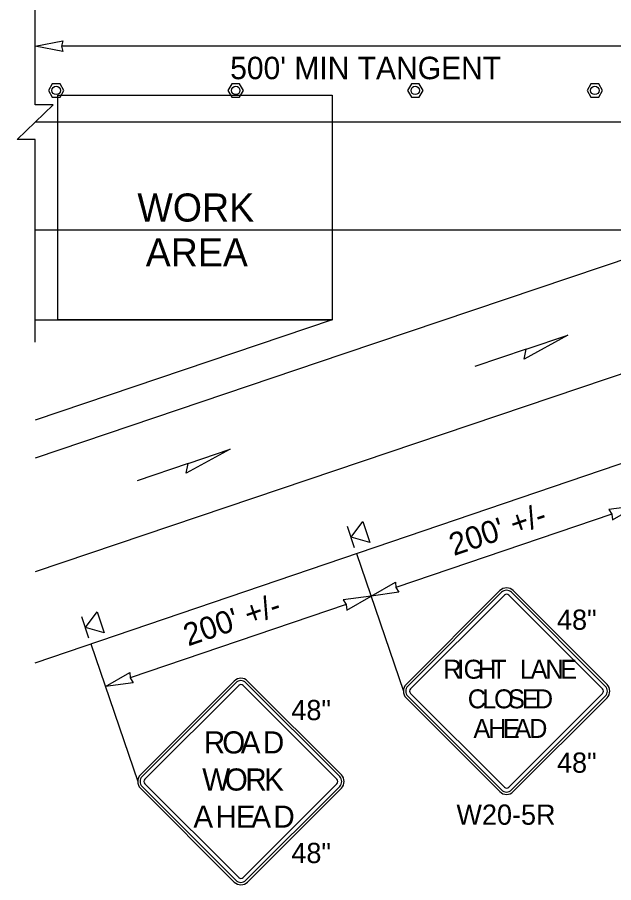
# Model space of a CAD drawing. Extents: x 99999 to 100116, y 99995 to 100013.
# Drawn here: x 100068.131 to 100070.257, y 100004.786 to 100007.868 of the extents above; entities that cross this region are included whole.
import ezdxf

# ---------------------------------------------------------------- set-up
doc = ezdxf.new("R2010")
doc.units = 0
for name, color, linetype in [('RD_MK_LineEdgeYellow', 7, 'Continuous'), ('RD_MK_LineLane', 7, 'Continuous'), ('TR_SN_ConstructionSigns', 7, 'Continuous'), ('TR_WZ_PortableSignMountBlk-Org', 7, 'Continuous'), ('TR_WZ_TallChanDevice', 7, 'Continuous'), ('TR_WZ_WorkAreaLabel', 7, 'Continuous'), ('TR_WZ_WorkZoneDetails', 7, 'Continuous'), ('TR_WZ_WorkZoneTextCurrent', 7, 'Continuous')]:
    doc.layers.add(name, color=color, linetype=linetype)

msp = doc.modelspace()

# ---------------------------------------------------------------- linework, layer by layer
at = {"layer": 'RD_MK_LineEdgeYellow'}
for p, q in [((100068.195, 100007.1109), (100069.2533, 100007.1109)), ((100070.6655, 100006.7269), (100068.195, 100005.8927)), ((100069.2943, 100006.6692), (100068.195, 100006.298))]:
    msp.add_line(p, q, dxfattribs=at)
at = {"layer": 'RD_MK_LineLane'}
msp.add_lwpolyline([(100075.43, 100007.4949), (100068.195, 100007.4949)], dxfattribs=at)
at = {"layer": 'TR_SN_ConstructionSigns'}
for p, q in [((100069.8509, 100005.8261), (100069.5168, 100005.492)), ((100069.8568, 100005.8202), (100069.5227, 100005.4861)), ((100070.2267, 100005.4861), (100069.8926, 100005.8202)), ((100070.2327, 100005.492), (100069.8986, 100005.8261)), ((100069.5327, 100005.4761), (100069.8668, 100005.8102)), ((100069.8827, 100005.8102), (100070.2168, 100005.4761)), ((100068.9041, 100005.5043), (100068.57, 100005.1702)), ((100068.91, 100005.4983), (100068.5759, 100005.1642)), ((100068.5859, 100005.1543), (100068.92, 100005.4884)), ((100068.9359, 100005.4884), (100069.27, 100005.1543)), ((100069.28, 100005.1642), (100068.9458, 100005.4983)), ((100069.2859, 100005.1702), (100068.9518, 100005.5043)), ((100069.5227, 100005.4503), (100069.8568, 100005.1162)), ((100069.8668, 100005.1261), (100069.5327, 100005.4602)), ((100070.2168, 100005.4602), (100069.8827, 100005.1261)), ((100069.8926, 100005.1162), (100070.2267, 100005.4503)), ((100069.5168, 100005.4443), (100069.8509, 100005.1102)), ((100069.8986, 100005.1102), (100070.2327, 100005.4443)), ((100068.57, 100005.1224), (100068.9041, 100004.7883)), ((100068.5759, 100005.1284), (100068.91, 100004.7943)), ((100068.92, 100004.8043), (100068.5859, 100005.1384)), ((100069.27, 100005.1384), (100068.9359, 100004.8043)), ((100068.9458, 100004.7943), (100069.28, 100005.1284)), ((100068.9518, 100004.7883), (100069.2859, 100005.1224))]:
    msp.add_line(p, q, dxfattribs=at)
for centre, radius, start, end in [((100069.8747, 100005.8023), 0.0338, 45, 135), ((100069.8747, 100005.8023), 0.0253, 45, 135), ((100069.8747, 100005.8023), 0.0113, 45, 135), ((100068.9279, 100005.4804), 0.0338, 45, 135), ((100068.9279, 100005.4804), 0.0253, 45, 135), ((100068.9279, 100005.4804), 0.0113, 45, 135), ((100069.5406, 100005.4682), 0.0338, 135, 225), ((100069.5406, 100005.4682), 0.0253, 135, 225), ((100070.2088, 100005.4682), 0.0253, 315, 45), ((100070.2088, 100005.4682), 0.0338, 315, 45), ((100069.5406, 100005.4682), 0.0113, 135, 225), ((100070.2088, 100005.4682), 0.0113, 315, 45), ((100068.5938, 100005.1463), 0.0338, 135, 225), ((100068.5938, 100005.1463), 0.0253, 135, 225), ((100068.5938, 100005.1463), 0.0113, 135, 225), ((100069.2621, 100005.1463), 0.0113, 315, 45), ((100069.2621, 100005.1463), 0.0253, 315, 45), ((100069.2621, 100005.1463), 0.0338, 315, 45), ((100069.8747, 100005.1341), 0.0338, 225, 315), ((100069.8747, 100005.1341), 0.0253, 225, 315), ((100069.8747, 100005.1341), 0.0113, 225, 315), ((100068.9279, 100004.8122), 0.0113, 225, 315), ((100068.9279, 100004.8122), 0.0338, 225, 315), ((100068.9279, 100004.8122), 0.0253, 225, 315)]:
    msp.add_arc(centre, radius, start, end, dxfattribs=at)
at = {"layer": 'TR_WZ_PortableSignMountBlk-Org'}
for p, q in [((100069.3333, 100005.9787), (100069.3076, 100006.0545)), ((100068.3865, 100005.6569), (100068.3608, 100005.7326))]:
    msp.add_line(p, q, dxfattribs=at)
for points in [[(100069.3205, 100006.0165), (100069.362, 100006.0729), (100069.3877, 100005.9972)], [(100068.3737, 100005.6947), (100068.4152, 100005.7511), (100068.4409, 100005.6753)]]:
    msp.add_lwpolyline(points, close=True, dxfattribs=at)
at = {"layer": 'TR_WZ_TallChanDevice'}
for points in [[(100068.2833, 100007.6319), (100068.2555, 100007.6319), (100068.2417, 100007.6079), (100068.2555, 100007.5839), (100068.2833, 100007.5839), (100068.2971, 100007.6079)], [(100068.9233, 100007.6319), (100068.8955, 100007.6319), (100068.8817, 100007.6079), (100068.8955, 100007.5839), (100068.9233, 100007.5839), (100068.9371, 100007.6079)], [(100069.5633, 100007.6319), (100069.5355, 100007.6319), (100069.5217, 100007.6079), (100069.5355, 100007.5839), (100069.5633, 100007.5839), (100069.5771, 100007.6079)], [(100070.2033, 100007.6319), (100070.1755, 100007.6319), (100070.1617, 100007.6079), (100070.1755, 100007.5839), (100070.2033, 100007.5839), (100070.2171, 100007.6079)]]:
    msp.add_lwpolyline(points, close=True, dxfattribs=at)
for points in [[(100068.2833, 100007.6319), (100068.2555, 100007.6319), (100068.2417, 100007.6079), (100068.2555, 100007.5839), (100068.2833, 100007.5839), (100068.2971, 100007.6079), (100068.2833, 100007.6319)], [(100068.9233, 100007.6319), (100068.8955, 100007.6319), (100068.8817, 100007.6079), (100068.8955, 100007.5839), (100068.9233, 100007.5839), (100068.9371, 100007.6079), (100068.9233, 100007.6319)], [(100069.5633, 100007.6319), (100069.5355, 100007.6319), (100069.5217, 100007.6079), (100069.5355, 100007.5839), (100069.5633, 100007.5839), (100069.5771, 100007.6079), (100069.5633, 100007.6319)], [(100070.2033, 100007.6319), (100070.1755, 100007.6319), (100070.1617, 100007.6079), (100070.1755, 100007.5839), (100070.2033, 100007.5839), (100070.2171, 100007.6079), (100070.2033, 100007.6319)]]:
    msp.add_lwpolyline(points, dxfattribs=at)
for centre in [(100068.2694, 100007.6079), (100068.9094, 100007.6079), (100069.5494, 100007.6079), (100070.1894, 100007.6079)]:
    msp.add_circle(centre, 0.015, dxfattribs=at)
at = {"layer": 'TR_WZ_WorkZoneDetails'}
for p, q in [((100070.5087, 100007.7659), (100068.2887, 100007.7659)), ((100069.2533, 100007.1109), (100070.6024, 100007.1109)), ((100070.6024, 100007.1109), (100069.2943, 100006.6692)), ((100068.195, 100006.7909), (100069.2533, 100006.7909)), ((100069.2533, 100006.7909), (100068.195, 100006.4338)), ((100069.9441, 100006.6859), (100069.7613, 100006.6242)), ((100068.195, 100005.5689), (100070.6601, 100006.4069)), ((100068.7404, 100006.2795), (100068.5576, 100006.2178)), ((100070.2498, 100006.0985), (100069.4805, 100005.8369)), ((100069.3403, 100005.9583), (100069.5069, 100005.4682)), ((100069.303, 100005.7766), (100068.5337, 100005.5151)), ((100068.3935, 100005.6364), (100068.5601, 100005.1463))]:
    msp.add_line(p, q, dxfattribs=at)
msp.add_lwpolyline([(100068.195, 100006.7109), (100068.195, 100007.433), (100068.131, 100007.433), (100068.259, 100007.5569), (100068.195, 100007.5569), (100068.195, 100008.0869)], dxfattribs=at)
for points in [[(100068.195, 100007.7659), (100068.2933, 100007.7851), (100068.2887, 100007.7659), (100068.2933, 100007.7466)], [(100068.275, 100006.7909), (100068.275, 100007.5909), (100069.2533, 100007.5909), (100069.2533, 100006.7909)], [(100070.093, 100006.7362), (100069.9371, 100006.651), (100069.9441, 100006.6859)], [(100068.8893, 100006.3298), (100068.7333, 100006.2445), (100068.7404, 100006.2795)], [(100070.3386, 100006.1286), (100070.2393, 100006.1152), (100070.2498, 100006.0985), (100070.2517, 100006.0787)], [(100069.3918, 100005.8068), (100069.4786, 100005.8567), (100069.4805, 100005.8369), (100069.491, 100005.8202)], [(100069.3918, 100005.8068), (100069.2925, 100005.7934), (100069.303, 100005.7766), (100069.3049, 100005.7569)], [(100068.445, 100005.4849), (100068.5318, 100005.5348), (100068.5337, 100005.5151), (100068.5442, 100005.4983)]]:
    msp.add_lwpolyline(points, close=True, dxfattribs=at)

# ---------------------------------------------------------------- texts
at = {"layer": 'TR_SN_ConstructionSigns'}
for s, height, p in [('48"', 0.072, (100070.0545, 100005.6867)), ('R', 0.0675, (100069.6493, 100005.5125)), ('I', 0.0675, (100069.6986, 100005.5125)), ('G', 0.0675, (100069.7215, 100005.5125)), ('H', 0.0675, (100069.7728, 100005.5125)), ('T', 0.0675, (100069.8201, 100005.5125)), ('L', 0.0675, (100069.922, 100005.5125)), ('A', 0.0675, (100069.9605, 100005.5125)), ('N', 0.0675, (100070.0131, 100005.5125)), ('E', 0.0675, (100070.0658, 100005.5125)), ('C', 0.0675, (100069.7364, 100005.407)), ('L', 0.0675, (100069.7877, 100005.407)), ('O', 0.0675, (100069.8302, 100005.407)), ('S', 0.0675, (100069.8801, 100005.407)), ('E', 0.0675, (100069.9294, 100005.407)), ('D', 0.0675, (100069.9753, 100005.407)), ('48"', 0.072, (100069.1077, 100005.3649)), ('A', 0.0675, (100069.7566, 100005.3015)), ('H', 0.0675, (100069.8093, 100005.3015)), ('E', 0.0675, (100069.8619, 100005.3015)), ('A', 0.0675, (100069.9024, 100005.3015)), ('D', 0.0675, (100069.9551, 100005.3015)), ('O', 0.0788, (100068.8614, 100005.2462)), ('R', 0.0788, (100068.796, 100005.2462)), ('A', 0.0788, (100068.9276, 100005.2462)), ('D', 0.0788, (100069.0063, 100005.2462)), ('48"', 0.072, (100070.0545, 100005.1776)), ('W', 0.0788, (100068.7901, 100005.114)), ('O', 0.0788, (100068.8705, 100005.114)), ('R', 0.0788, (100068.9437, 100005.114)), ('K', 0.0788, (100069.0106, 100005.114)), ('A', 0.0788, (100068.7586, 100004.9818)), ('H', 0.0788, (100068.8374, 100004.9818)), ('E', 0.0788, (100068.9098, 100004.9818)), ('A', 0.0788, (100068.965, 100004.9818)), ('D', 0.0788, (100069.0437, 100004.9818)), ('W20-5R', 0.072, (100069.6961, 100004.9923)), ('48"', 0.072, (100069.1077, 100004.8558))]:
    msp.add_text(s, height=height, rotation=360, dxfattribs=at).set_placement(p)
at = {"layer": 'TR_WZ_WorkAreaLabel'}
for s, p in [('WORK', (100068.559, 100007.1409)), ('AREA', (100068.5887, 100006.9809))]:
    msp.add_text(s, height=0.1, dxfattribs=at).set_placement(p)
at = {"layer": 'TR_WZ_WorkZoneTextCurrent'}
msp.add_text("500' MIN TANGENT", height=0.08, dxfattribs=at).set_placement((100068.8897, 100007.6479))
for p in [(100069.6866, 100005.9492), (100068.7398, 100005.6274)]:
    msp.add_text("200' +/-", height=0.08, rotation=18.775, dxfattribs=at).set_placement(p)

doc.saveas('drawing.dxf')
